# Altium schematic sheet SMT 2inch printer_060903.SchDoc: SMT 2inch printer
size A3
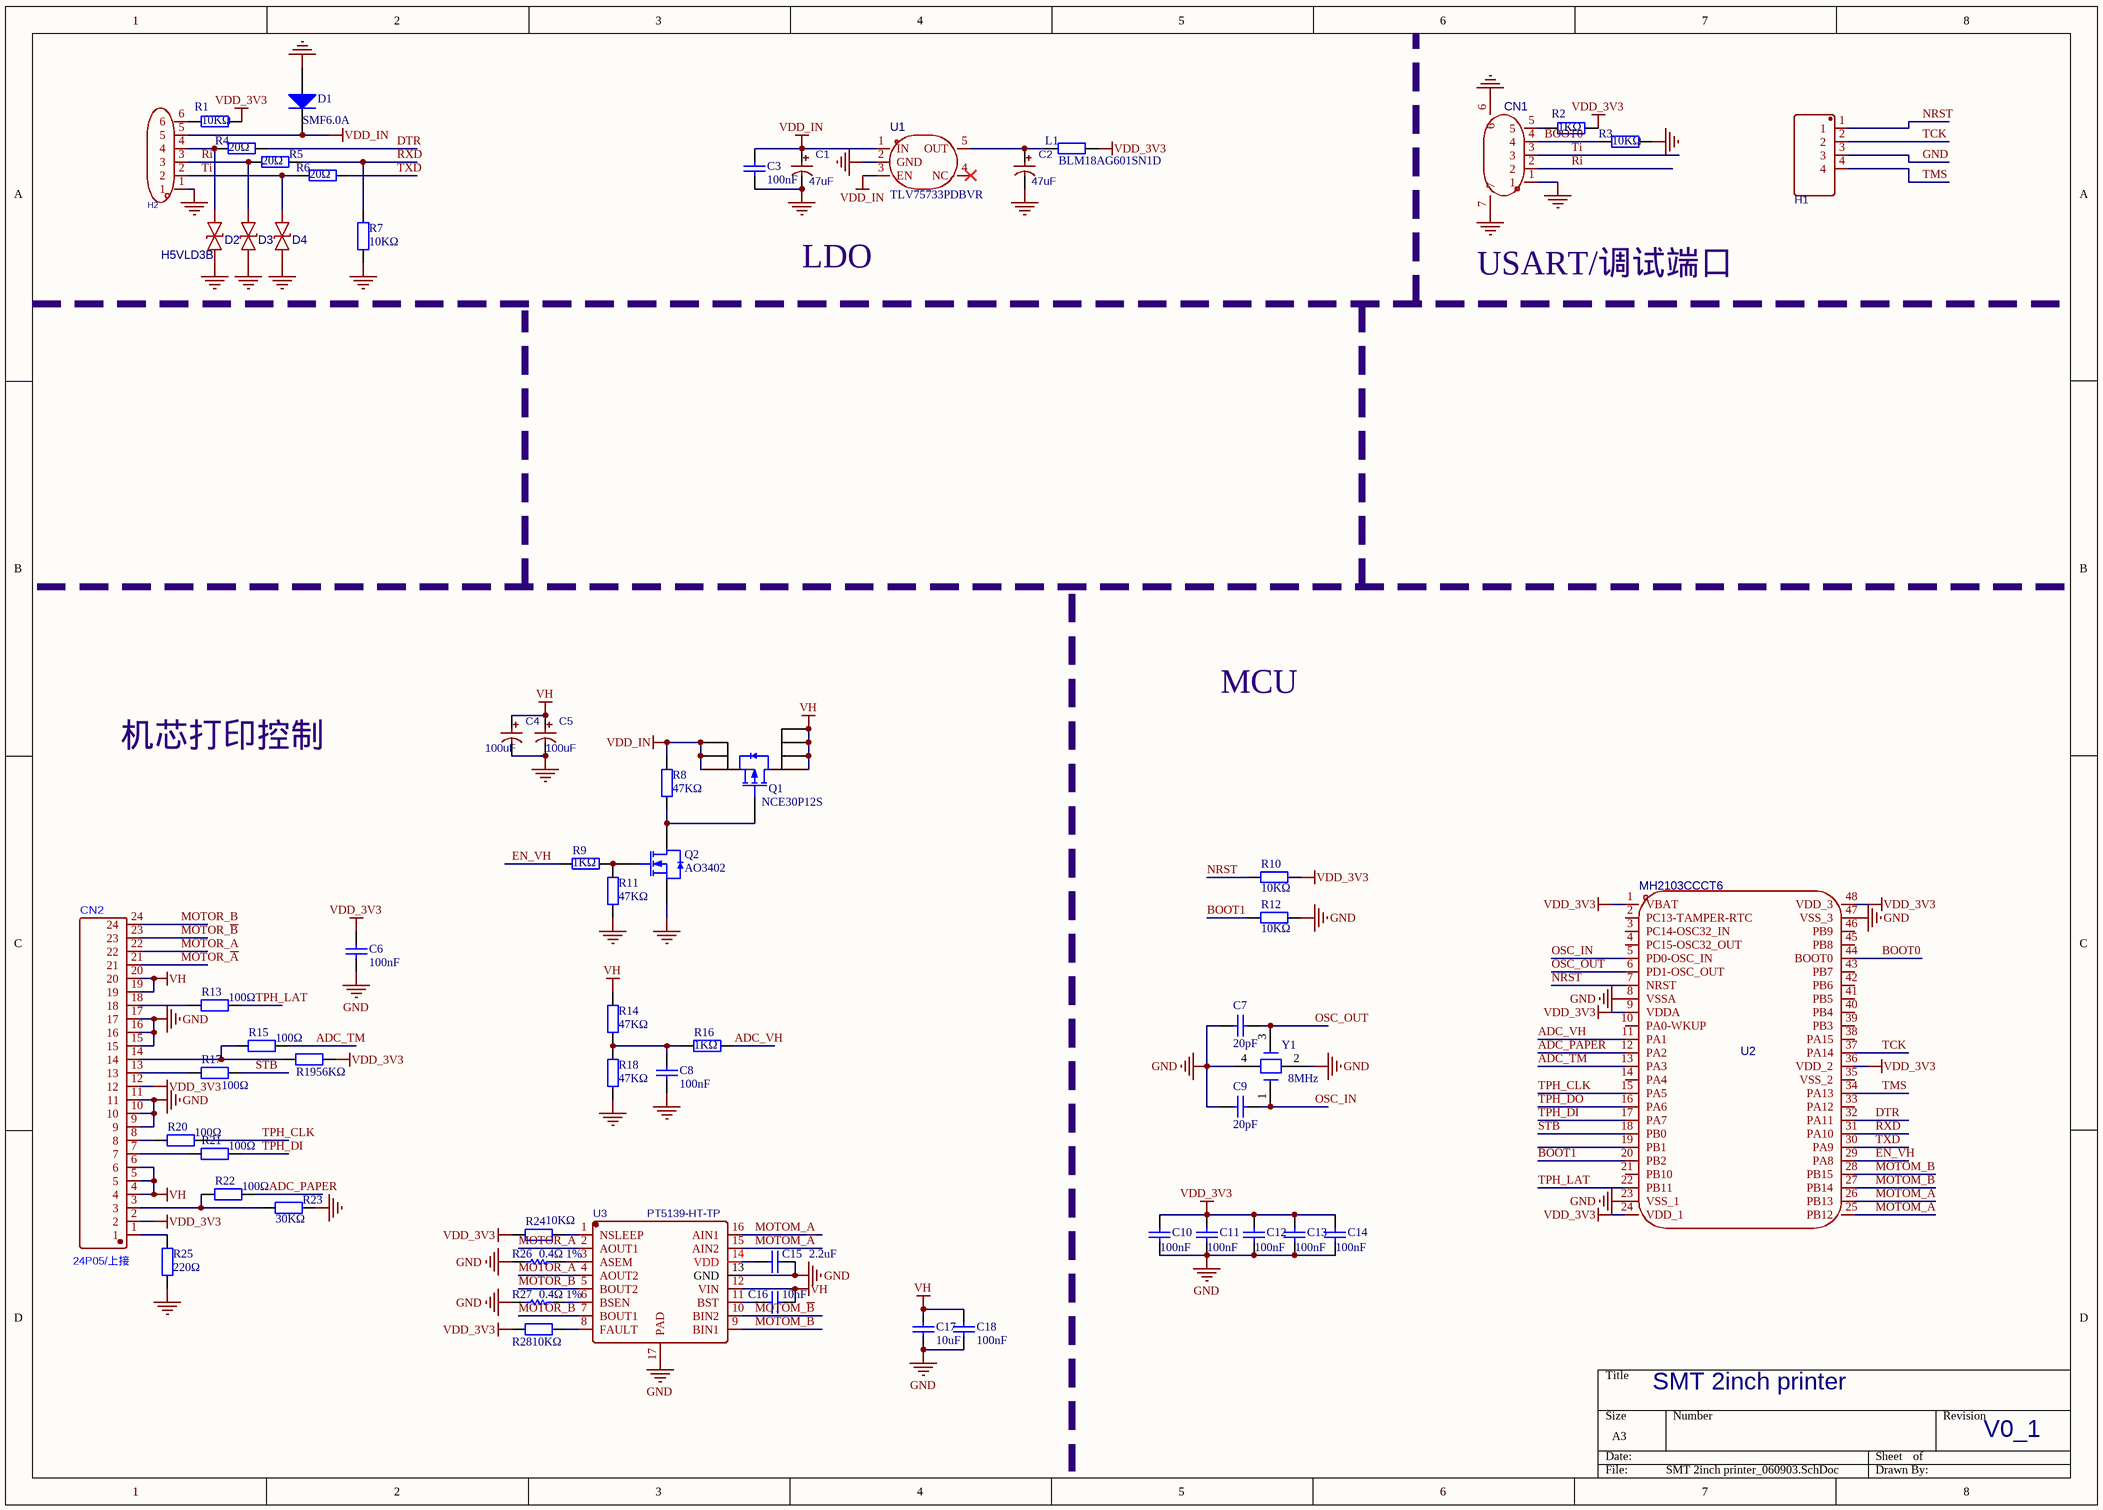
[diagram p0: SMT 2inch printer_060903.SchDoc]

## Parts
C1  47uF  [CAP-SMD_BD6.3-L6.6-W6.6-FD]
C2  47uF  [CAP-SMD_BD6.3-L6.6-W6.6-FD]
C3  100nF  [0603_C]
C4  100uF  [CAP-SMD_BD6.3-L6.6-W6.6-FD]
C5  100uF  [CAP-SMD_BD6.3-L6.6-W6.6-FD]
C6  100nF  [0603_C]
C7  20pF  [0603_C]
C8  100nF  [0603_C]
C9  20pF  [0603_C]
C10  100nF  [0603_C]
C11  100nF  [0603_C]
C12  100nF  [0603_C]
C13  100nF  [0603_C]
C14  100nF  [0603_C]
C15  2.2uF  [0603_C]
C16  10nF  [0603_C]
C17  10uF  [0603_C]
C18  100nF  [0603_C]
CN1  mx1.25mm-5p-wt  [CONN-SMD_5P-P1.25_MX1.25MM-5P-WT]  (value not drawn)
CN2  24P05/上接  [FPC-SMD_24P-P0.50_F0500WR-S-24PNLNG1GB0R]
D1  SMF6.0A  [SOD-123FL_L2.7-W1.8-LS3.8-RD]
D2  H5VLD3B  [SOD-323_L1.7-W1.3-LS2.5-BI]
D3  H5VLD3B  [SOD-323_L1.7-W1.3-LS2.5-BI]  (value not drawn)
D4  H5VLD3B  [SOD-323_L1.7-W1.3-LS2.5-BI]  (value not drawn)
H1  77311-462K05LF  [77311-462K05LF]  (value not drawn)
H2  lail-pz2.54-6p-l  [HDR-TH_6P-P2.54-V-F]  (value not drawn)
L1  BLM18AG601SN1D  [0805_L]
Q1  NCE30P12S  [SOIC-8_150mil]
Q2  AO3402  [SOT-23-3L]
R1  10KΩ  [0603_R]
R2  1KΩ  [0603_R]
R3  10KΩ  [0603_R]
R4  20Ω  [0603_R]
R5  20Ω  [0603_R]
R6  20Ω  [0603_R]
R7  10KΩ  [0603_R]
R8  47KΩ  [0603_R]
R9  1KΩ  [0603_R]
R10  10KΩ  [0603_R]
R11  47KΩ  [0603_R]
R12  10KΩ  [0603_R]
R13  100Ω  [0603_R]
R14  47KΩ  [0603_R]
R15  100Ω  [0603_R]
R16  1KΩ  [0603_R]
R17  100Ω  [0603_R]
R18  47KΩ  [0603_R]
R19  56KΩ  [0603_R]
R20  100Ω  [0603_R]
R21  100Ω  [0603_R]
R22  100Ω  [0603_R]
R23  30KΩ  [0603_R]
R24  10KΩ  [0603_R]
R25  220Ω  [0603_R]
R26  0.4Ω 1%  [1206_R]
R27  0.4Ω 1%  [1206_R]
R28  10KΩ  [0603_R]
U1  TLV75733PDBVR  [SOT-23-5]
U2  MH2103CCCT6  [LQFP-48_L7.0-W7.0-P0.50-LS9.0-BL]
U3  PT5139-HT-TP  [HTSSOP-16_L5.0-W4.4-P0.65-LS6.4-BL-EP]
Y1  8MHz  [XT_3225_4]

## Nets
GND: C1.2 C2.2 C3.2 C4.2 C5.2 C6.1 C7.1 C8.1 C9.1 C10.1 C11.1 C12.1 C13.1 C14.1 C15.2 C17.1 C18.1 CN1.1 CN1.6 CN1.7 CN2.9 CN2.10 CN2.11 CN2.15 CN2.16 CN2.17 D1.1(A) D2.1 D3.1 D4.1 H1.3 H2.1 Q2.2(S) R3.2 R7.1 R11.2 R12.1 R18.2 R23.2 R25.1 R26.2 R27.2 U1.2(GND) U2.8(VSSA) U2.23(VSS_1) U2.47(VSS_3) U3.13(GND) U3.17(PAD) Y1.2 Y1.4
VDD_3V3: C6.2 C10.2 C11.2 C12.2 C13.2 C14.2 CN2.2 CN2.12 L1.2 R1.2 R2.2 R10.1 R19.2 R24.2 R28.2 U2.1(VBAT) U2.9(VDDA) U2.24(VDD_1) U2.36(VDD_2) U2.48(VDD_3)
VDD_IN: C1.1 C3.1 D1.2(K) H2.5 Q1.1(S) Q1.2(S) Q1.3(S) R8.2 U1.1(IN) U1.3(EN)
VH: C4.1 C5.1 C16.2 C17.2 C18.2 CN2.4 CN2.5 CN2.6 CN2.19 CN2.20 Q1.5(D) Q1.6(D) Q1.7(D) Q1.8(D) R14.1 U3.12(VIN)
ADC_PAPER: R22.2 U2.12(PA2)
ADC_TM: R15.2 U2.13(PA3)
ADC_VH: R16.1 U2.11(PA1)
BOOT0: CN1.4 R3.1 U2.44(BOOT0)
BOOT1: R12.2 U2.20(PB2)
DTR: R4.2 U2.32(PA11)
EN_VH: R9.2 U2.29(PA8)
MOTOM_A: U2.25(PB12) U3.16(AIN1)
MOTOM_~{A}: U2.26(PB13) U3.15(AIN2)
MOTOM_B: U2.28(PB15) U3.9(BIN1)
MOTOM_~{B}: U2.27(PB14) U3.10(BIN2)
MOTOR_A: CN2.22 U3.2(AOUT1)
MOTOR_~{A}: CN2.21 U3.4(AOUT2)
MOTOR_B: CN2.24 U3.7(BOUT1)
MOTOR_~{B}: CN2.23 U3.5(BOUT2)
NRST: H1.1 R10.2 U2.7(NRST)
OSC_IN: C9.2 U2.5(PD0-OSC_IN) Y1.1(OSC1)
OSC_OUT: C7.2 U2.6(PD1-OSC_OUT) Y1.3(OSC2)
Ri: CN1.2 D3.2 H2.3 R5.1
RXD: R5.2 R7.2 U2.31(PA10)
STB: R17.2 U2.18(PB0)
TCK: H1.2 U2.37(PA14)
Ti: CN1.3 D4.2 H2.2 R6.1
TMS: H1.4 U2.34(PA13)
TPH_CLK: R20.2 U2.15(PA5)
TPH_DI: R21.2 U2.17(PA7)
TPH_DO: U2.16(PA6)
TPH_LAT: R13.2 U2.22(PB11)
TXD: R6.2 U2.30(PA9)
NetC2_1: C2.1 L1.1 U1.5(OUT)
NetC8_2: C8.2 R14.2 R16.2 R18.1
NetC15_1: C15.1 U3.14(VDD)
NetC16_1: C16.1 U3.11(BST)
NetCN1_5: CN1.5 R2.1
NetCN2_1: CN2.1 R25.2
NetCN2_3: CN2.3 R22.1 R23.1
NetCN2_7: CN2.7 R21.1
NetCN2_8: CN2.8 R20.1
NetCN2_13: CN2.13 R17.1
NetCN2_14: CN2.14 R15.1 R19.1
NetCN2_18: CN2.18 R13.1
NetD2_2: D2.2 H2.4 R4.1
NetH2_6: H2.6 R1.1
NetQ1_4: Q1.4(G) Q2.3(D) R8.1
NetQ2_1: Q2.1(G) R9.1 R11.1
NetR24_1: R24.1 U3.1(NSLEEP)
NetR26_1: R26.1 U3.3(ASEM)
NetR27_1: R27.1 U3.6(BSEN)
NetR28_1: R28.1 U3.8(FAULT)

Not connected (* = marked no-connect by the designer): U1 4(NC)*; U2 2(PC13-TAMPER-RTC) 3(PC14-OSC32_IN) 4(PC15-OSC32_OUT) 10(PA0-WKUP) 14(PA4) 19(PB1) 21(PB10) 33(PA12) 35(VSS_2) 38(PA15) 39(PB3) 40(PB4) 41(PB5) 42(PB6) 43(PB7) 45(PB8) 46(PB9)

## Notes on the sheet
- LDO
- (near CN1) USART/调试端口
- MCU
- 机芯打印控制
- SMT 2inch printer
- V0_1

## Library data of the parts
C1 C2 C4 C5 = 10uF: BOM_Manufacturer: ValuePro; BOM_Manufacturer Part: 10uF 25V RHOS; nameAlias: Capacitance
C3 C6 C8 C10-C14 C18 = 0603 100nF (104) 10% 50V: 贴片电容
C7 C9 = 0603 10pF (100) 5% 50V: 贴片电容
C15 = 0805 2.2uF (225) 20% 50V: 贴片电容
C16 = 0603 10nF (103) 10% 50V: 贴片电容
C17 = 0805 10uF (106) 10% 25V: 贴片电容
CN1 = mx1.25mm-5p-wt: AddInBom: yes; Pins Structure: 1x5P; Pitch: 1.25mm; Reference Series: PicoBlade(MX 1.25); Number of PINs Per Row: 5; Current Rating: 1A; Voltage Rating: 125V; Plastic Material: LCP
D1 = SOD-323 1N4148WS T4: 稳压二极管
D2-D4 = PESD5V0S1BA_C2827694
H1 = 77311-462K05LF: BOM_Manufacturer: Amphenol ICC; Contributor: LCSC
H2 = lail-pz2.54-6p-l: AddInBom: yes; ModelId: 78d66b34ad7c4f8faa1ccf54151694d8; ModelName: CONN-TH_LAIL-PZ2.54-6P-L; ModelTransform: 599.999,98.8187,0,0,0,0,0,0,-118.11; Pin Structure: 1x6P; Pitch: 2.54mm; Current Rating: 3A; Voltage Rating (Max): 250V
L1 R1-R3 R7 R10-R12 R14 R18 = 0603 4.7KΩ (4701) 1%: 贴片电阻
Q1 = AO4407A: MOS(场效应管)
Q2 = AO3402A N道沟 X0YV1T SOT-23: MOS(场效应管)
R4-R6 = 0603 100Ω (1000) 1%: 贴片电阻
R8 = 0603 47KΩ (4702) 1%: 贴片电阻
R9 R16 = 0603 470Ω (4700) 1%: 贴片电阻
R13 R15 R17 R19-R22 R24 R28 = 0603 10KΩ (1002) 1%: 贴片电阻
R23 = 0603 30KΩ (3002) 1%: 贴片电阻
R25 = 0603 200Ω (2000) 1%: 贴片电阻
R26 R27 = Res: Resistor; Value: 1K
U2 = stm32f103c8t6: AddInBom: yes; ModelId: 093be70396ff421eb2cdb946d5311efc; ModelName: LQFP-48_L7.0-W7.0-H1.4-LS9.0-P0.50; ModelTransform: 354.331,354.331,0,0,0,0,0,0,0; CPU Core: ARM Cortex-M3; CPU Maximum Speed: 72MHz; Core Size: 32 Bit; Program Storage Size: 64KB; Program Memory Type: FLASH; RAM Size: 20KB; Number of I/O: 37; ADC (Bit): 12bit; Voltage - Supply: 2V~3.6V
U3 = PT5139-HT-TP: BOM_Manufacturer: Princeton Tech; Contributor: LCSC
Y1 = XTAL_4: Crystal Oscillator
